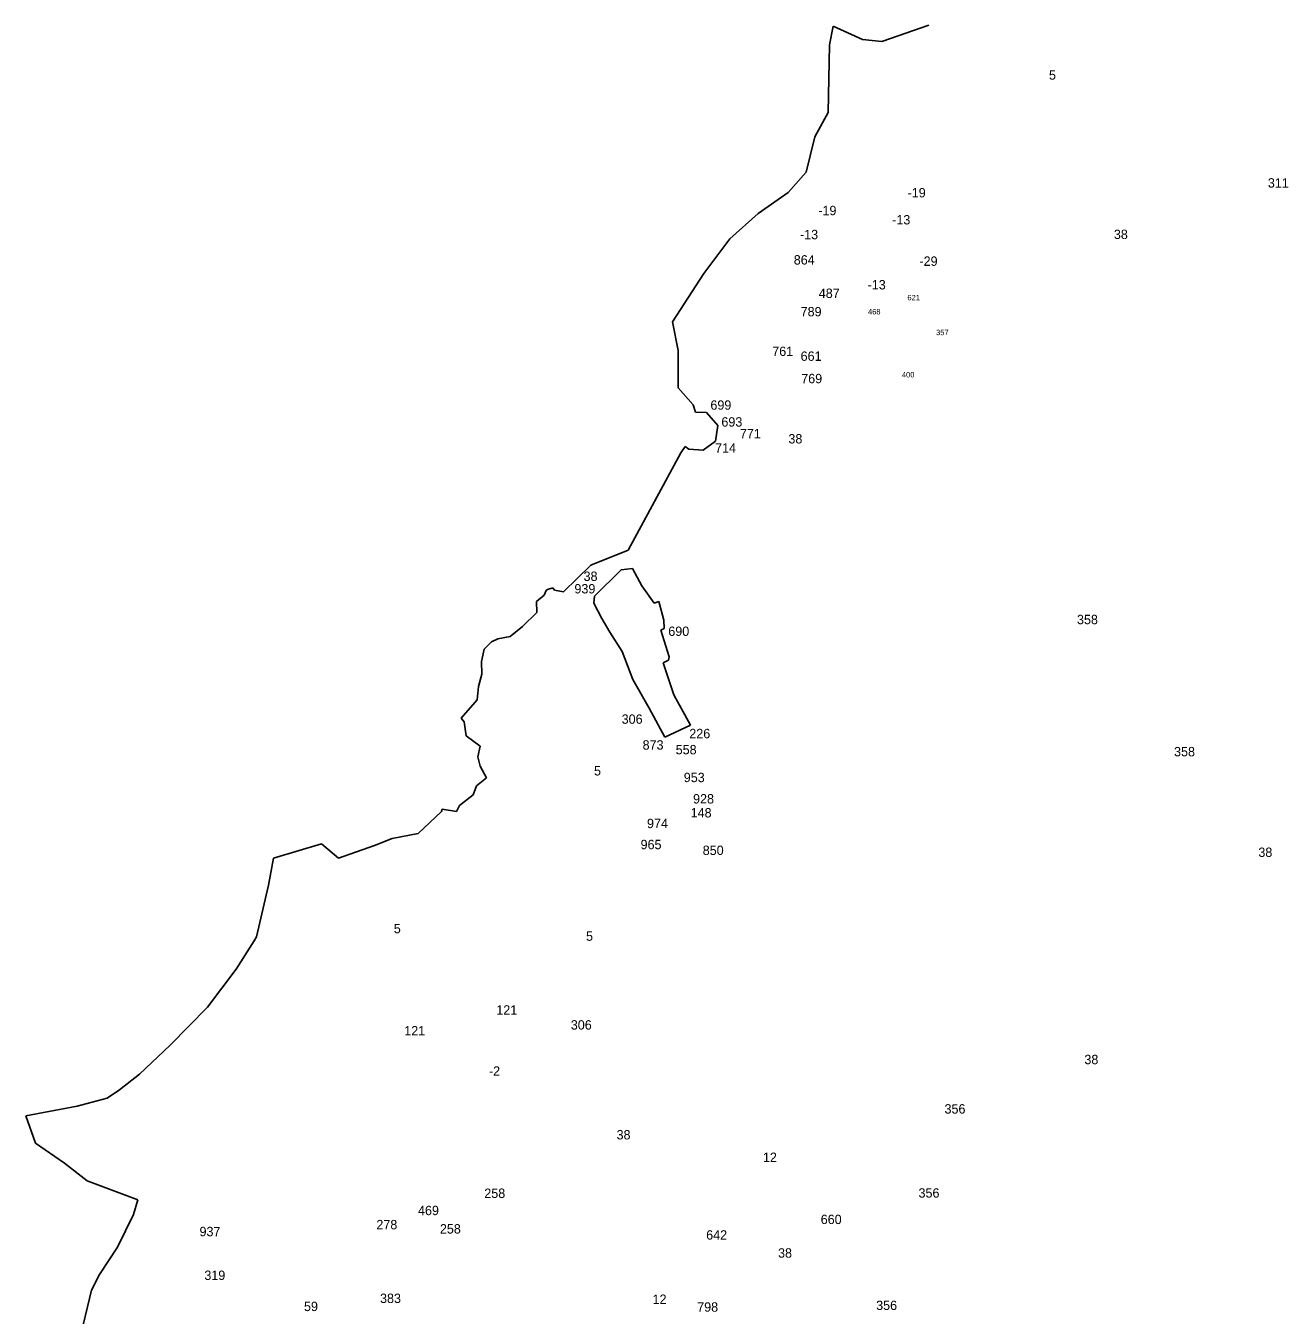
# Model space of a CAD drawing. Extents: x -782977 to -778030, y -975420 to -964838.
# Drawn here: x -781315 to -780386, y -973722 to -972772 of the extents above; entities that cross this region are included whole.
import ezdxf

# ---------------------------------------------------------------- set-up
doc = ezdxf.new("R2010")
doc.units = 0
doc.layers.add('Vrstva 13', color=7, linetype='Continuous')
doc.layers.add('Vrstva 24', color=7, linetype='Continuous')

msp = doc.modelspace()

# ---------------------------------------------------------------- linework, layer by layer
at = {"layer": 'Vrstva 13'}
for p, q in [((-780723.65, -972785.44), (-780720.78, -972771.87)), ((-780720.78, -972771.87), (-780699.31, -972781.61)), ((-780684.87, -972783.05), (-780650.48, -972771.15)), ((-780724.61, -972835.44), (-780723.65, -972785.44)), ((-780699.31, -972781.61), (-780684.87, -972783.05)), ((-780734.35, -972853.38), (-780724.61, -972835.44)), ((-780740.74, -972879.41), (-780734.35, -972853.38)), ((-780753.91, -972894.34), (-780740.74, -972879.41)), ((-780776.09, -972909.75), (-780753.91, -972894.34)), ((-780796.92, -972928.55), (-780776.09, -972909.75)), ((-780816, -972954.14), (-780796.92, -972928.55)), ((-780839.14, -972989.74), (-780816, -972954.14)), ((-780834.91, -973010.81), (-780839.14, -972989.74)), ((-780835.03, -973038.3), (-780834.91, -973010.81)), ((-780824.01, -973050.8), (-780835.03, -973038.3)), ((-780822.13, -973056.18), (-780824.01, -973050.8)), ((-780814.11, -973056.5), (-780822.13, -973056.18)), ((-780805.73, -973065.97), (-780814.11, -973056.5)), ((-780807.44, -973077.55), (-780805.73, -973065.97)), ((-780816.46, -973084.3), (-780807.44, -973077.55)), ((-780871.72, -973157.85), (-780833.1, -973086.16)), ((-780833.1, -973086.16), (-780829.78, -973081.59)), ((-780829.78, -973081.59), (-780827.07, -973083.46)), ((-780827.07, -973083.46), (-780816.46, -973084.3)), ((-780899.41, -973168.91), (-780871.72, -973157.85)), ((-780919.44, -973188.71), (-780899.41, -973168.91)), ((-780896.68, -973191.79), (-780877.09, -973172.41)), ((-780877.09, -973172.41), (-780868.64, -973171.34)), ((-780868.64, -973171.34), (-780861.64, -973184.29)), ((-780931.17, -973186.82), (-780927.26, -973185.78)), ((-780927.26, -973185.78), (-780926.07, -973187.43)), ((-780861.64, -973184.29), (-780852.68, -973197.02)), ((-780939.26, -973195.69), (-780933.6, -973191.12)), ((-780933.6, -973191.12), (-780932.21, -973187.7)), ((-780932.21, -973187.7), (-780931.17, -973186.82)), ((-780926.07, -973187.43), (-780919.44, -973188.71)), ((-780897.07, -973197.01), (-780896.68, -973191.79)), ((-780949.76, -973214.2), (-780939.14, -973203.86)), ((-780939.14, -973203.86), (-780939.26, -973195.69)), ((-780891.16, -973208.31), (-780897.07, -973197.01)), ((-780852.68, -973197.02), (-780849.33, -973195.8)), ((-780849.33, -973195.8), (-780845.66, -973209.64)), ((-780958.69, -973221.59), (-780949.76, -973214.2)), ((-780885.26, -973218.29), (-780891.16, -973208.31)), ((-780845.66, -973209.64), (-780845.25, -973215.75)), ((-780972.5, -973225.58), (-780967.75, -973223.39)), ((-780967.75, -973223.39), (-780958.69, -973221.59)), ((-780876.3, -973232.65), (-780885.26, -973218.29)), ((-780845.25, -973215.75), (-780847.7, -973216.97)), ((-780847.7, -973216.97), (-780841.67, -973236.45)), ((-780979.88, -973239.87), (-780977.89, -973230.85)), ((-780977.89, -973230.85), (-780972.5, -973225.58)), ((-780868.47, -973253.22), (-780876.3, -973232.65)), ((-780979.6, -973249.33), (-780979.88, -973239.87)), ((-780842.18, -973238.94), (-780846.15, -973240.88)), ((-780846.15, -973240.88), (-780838.26, -973264.6)), ((-780841.67, -973236.45), (-780842.18, -973238.94)), ((-780982, -973258.42), (-780979.6, -973249.33)), ((-780982.95, -973268.24), (-780982, -973258.42)), ((-780856.36, -973274.3), (-780868.47, -973253.22)), ((-780994.76, -973281.67), (-780982.95, -973268.24)), ((-780838.26, -973264.6), (-780825.9, -973286.95)), ((-780844.78, -973295.86), (-780856.36, -973274.3)), ((-780992.62, -973284.34), (-780994.76, -973281.67)), ((-780991.06, -973294.67), (-780992.62, -973284.34)), ((-780825.9, -973286.95), (-780844.78, -973295.86)), ((-780980.85, -973302.43), (-780991.06, -973294.67)), ((-780982.61, -973310.29), (-780980.85, -973302.43)), ((-780980.73, -973317.15), (-780982.61, -973310.29)), ((-780976.06, -973325.7), (-780980.73, -973317.15)), ((-780983.48, -973331.61), (-780976.06, -973325.7)), ((-780985.94, -973338.33), (-780983.48, -973331.61)), ((-780998.26, -973350.44), (-780996.03, -973346.21)), ((-780996.03, -973346.21), (-780985.94, -973338.33)), ((-781026.42, -973366.76), (-781009.27, -973350.64)), ((-781009.27, -973350.64), (-781008.8, -973348.89)), ((-781008.8, -973348.89), (-780998.26, -973350.44)), ((-781132.99, -973384.96), (-781097.64, -973374.43)), ((-781097.64, -973374.43), (-781085.27, -973384.97)), ((-781085.27, -973384.97), (-781058.66, -973375.7)), ((-781058.66, -973375.7), (-781045.61, -973370.47)), ((-781045.61, -973370.47), (-781026.42, -973366.76)), ((-781136.66, -973404.84), (-781132.99, -973384.96)), ((-781145.6, -973442.81), (-781136.66, -973404.84)), ((-781160.48, -973466.72), (-781147.15, -973445.92)), ((-781147.15, -973445.92), (-781145.6, -973442.81)), ((-781181.66, -973494.68), (-781160.48, -973466.72)), ((-781209.11, -973522.77), (-781181.66, -973494.68)), ((-781231.84, -973544.16), (-781209.11, -973522.77)), ((-781246.52, -973555.73), (-781231.84, -973544.16)), ((-781255.62, -973561.89), (-781246.52, -973555.73)), ((-781277.72, -973567.63), (-781255.62, -973561.89)), ((-781315.46, -973574.75), (-781277.72, -973567.63)), ((-781315.46, -973574.75), (-781308.23, -973594.91)), ((-781308.23, -973594.91), (-781287, -973609.57)), ((-781287, -973609.57), (-781270.32, -973622.69)), ((-781270.32, -973622.69), (-781232.94, -973636.6)), ((-781232.94, -973636.6), (-781236.19, -973647.54)), ((-781236.19, -973647.54), (-781247.88, -973671.69)), ((-781247.88, -973671.69), (-781261.25, -973691.83)), ((-781261.25, -973691.83), (-781267.09, -973703.17)), ((-781267.09, -973703.17), (-781276.09, -973741.07))]:
    msp.add_line(p, q, dxfattribs=at)

# ---------------------------------------------------------------- texts
at = {"layer": 'Vrstva 24'}
for s, height, p in [('5', 6.912, (-780561.9, -972811.242)), ('-19', 6.912, (-780666.026, -972897.975)), ('311', 6.912, (-780400.669, -972890.762)), ('-19', 6.912, (-780731.776, -972911.085)), ('-13', 6.912, (-780677.36, -972917.895)), ('-13', 6.912, (-780745.27, -972928.805)), ('38', 6.912, (-780514.086, -972928.662)), ('864', 6.912, (-780749.861, -972947.462)), ('-29', 6.912, (-780657.284, -972948.415)), ('487', 6.912, (-780731.422, -972972.082)), ('-13', 6.912, (-780695.47, -972965.795)), ('621', 4, (-780666.168, -972973.84)), ('789', 6.912, (-780744.795, -972985.632)), ('468', 4, (-780695.178, -972984.23)), ('357', 4, (-780645.024, -972999.49)), ('761', 6.912, (-780765.698, -973014.852)), ('661', 6.912, (-780744.808, -973018.422)), ('769', 6.912, (-780744.361, -973034.922)), ('400', 4, (-780670.191, -973030.66)), ('699', 6.912, (-780811.241, -973054.442)), ('693', 6.912, (-780803.165, -973066.892)), ('771', 6.912, (-780789.529, -973075.522)), ('714', 6.912, (-780807.765, -973086.042)), ('38', 6.912, (-780753.796, -973079.312)), ('38', 6.912, (-780904.666, -973180.632)), ('939', 6.912, (-780911.405, -973189.822)), ('690', 6.912, (-780842.267, -973221.152)), ('358', 6.912, (-780541.262, -973212.512)), ('306', 6.912, (-780876.611, -973285.892)), ('226', 6.912, (-780826.789, -973296.542)), ('873', 6.912, (-780861.179, -973304.942)), ('558', 6.912, (-780836.832, -973308.402)), ('358', 6.912, (-780469.762, -973309.872)), ('5', 6.912, (-780896.97, -973323.992)), ('953', 6.912, (-780830.859, -973328.892)), ('928', 6.912, (-780824.009, -973344.632)), ('974', 6.912, (-780857.938, -973362.802)), ('148', 6.912, (-780825.808, -973354.922)), ('965', 6.912, (-780862.675, -973378.322)), ('850', 6.912, (-780816.895, -973382.592)), ('38', 6.912, (-780407.666, -973384.032)), ('5', 6.912, (-781044.41, -973440.262)), ('5', 6.912, (-780902.86, -973445.822)), ('121', 6.912, (-780968.929, -973500.242)), ('121', 6.912, (-781036.749, -973515.552)), ('306', 6.912, (-780914.061, -973511.262)), ('38', 6.912, (-780535.816, -973536.762)), ('-2', 6.912, (-780974.35, -973545.245)), ('356', 6.912, (-780638.819, -973573.152)), ('38', 6.912, (-780880.346, -973592.192)), ('12', 6.912, (-780772.569, -973608.822)), ('258', 6.912, (-780977.792, -973635.312)), ('356', 6.912, (-780657.969, -973635.102)), ('469', 6.912, (-781026.608, -973648.012)), ('278', 6.912, (-781057.259, -973658.432)), ('660', 6.912, (-780729.997, -973654.562)), ('937', 6.912, (-781187.525, -973663.532)), ('258', 6.912, (-781010.482, -973661.542)), ('642', 6.912, (-780814.351, -973666.042)), ('38', 6.912, (-780761.436, -973679.332)), ('319', 6.912, (-781183.962, -973695.762)), ('383', 6.912, (-781054.572, -973712.742)), ('12', 6.912, (-780853.849, -973713.422)), ('59', 6.912, (-781110.573, -973718.692)), ('798', 6.912, (-780820.985, -973719.162)), ('356', 6.912, (-780689.159, -973717.912))]:
    msp.add_text(s, height=height, dxfattribs=at).set_placement(p)

doc.saveas('drawing.dxf')
